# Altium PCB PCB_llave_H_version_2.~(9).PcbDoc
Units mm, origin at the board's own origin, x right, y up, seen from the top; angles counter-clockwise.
Board outline 98.1 x 71.5 mm, 2 copper layers (Top Layer, Bottom Layer); 62 components, 35 nets, 186 pads, 5 vias.
Unrouted connection lines stored in the file: 45.
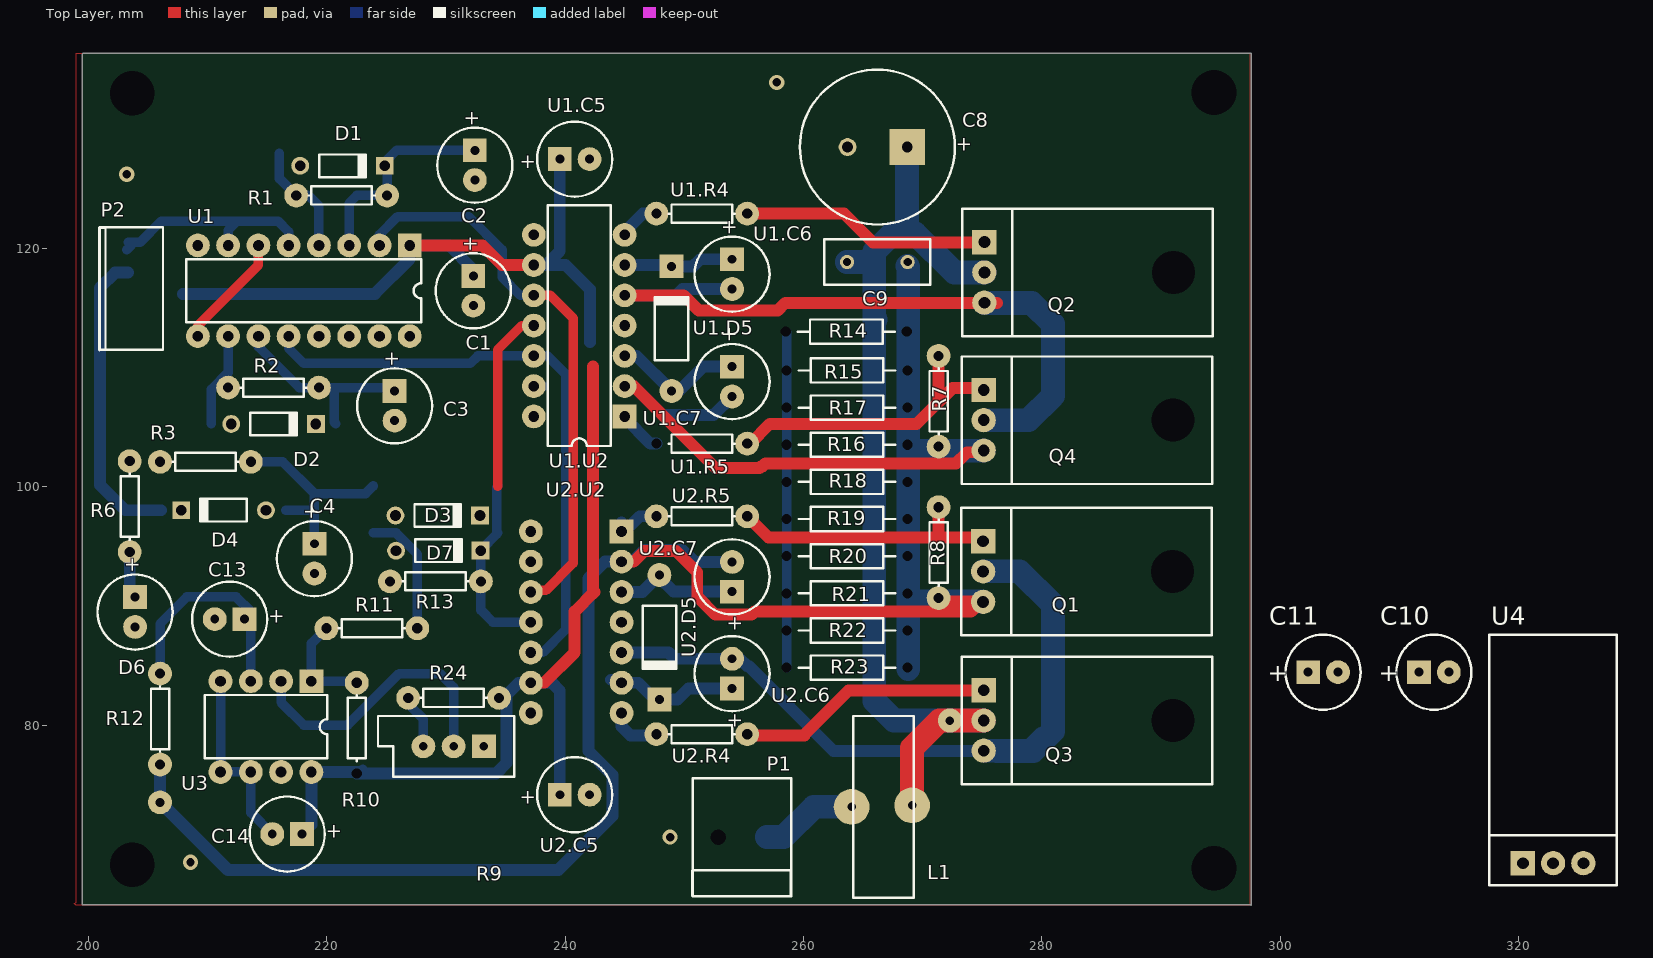
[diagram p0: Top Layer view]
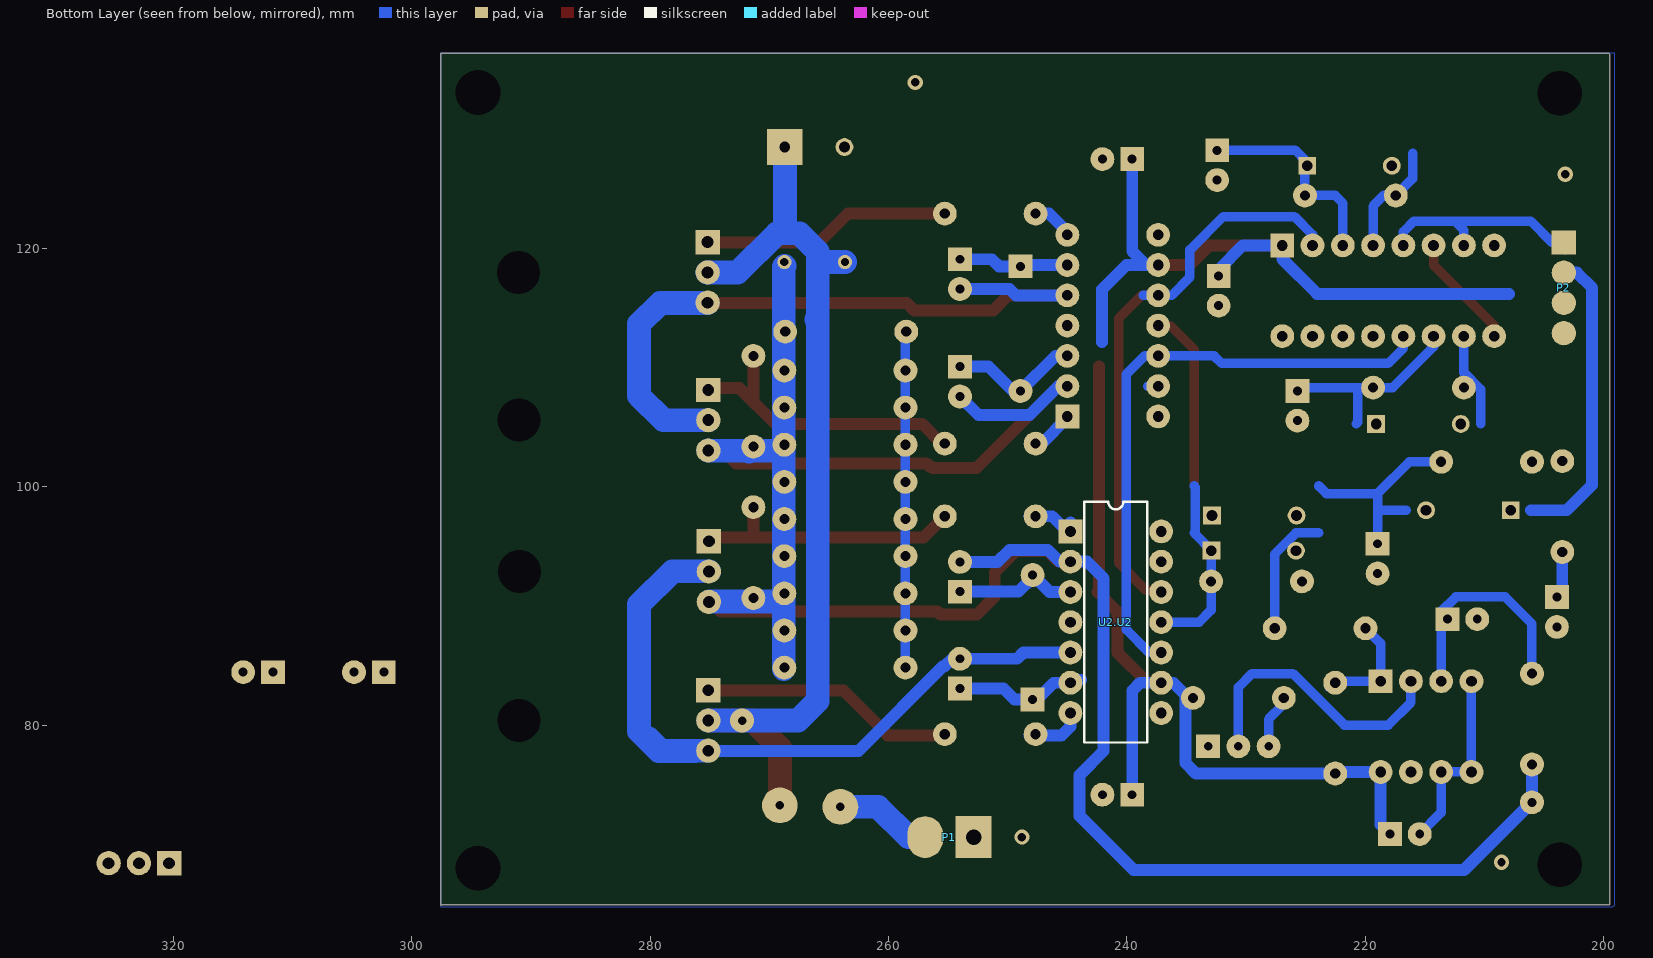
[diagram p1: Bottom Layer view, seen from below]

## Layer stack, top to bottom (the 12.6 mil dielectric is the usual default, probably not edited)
Top Layer: signal copper 0.0356
Dielectric: dielectric 0.32, FR-4, Dk 4.8
Bottom Layer: signal copper 0.0356

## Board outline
199.55,136.4 297.55,136.4 297.55,64.9 297.5,64.95 199.45,64.95 199.45,136.3

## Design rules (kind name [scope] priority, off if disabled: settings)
Clearance [All] p1: gap=0.4
ComponentClearance [All] p1: gap=0.254 collisioncheckmode=2 verticalgap=0.254
PlaneConnect [All] p1: planeconnectstyle=Direct reliefexpansion=0.508 reliefentries=4 reliefconductorwidth=0.254 reliefairgap=0.254
PolygonConnect [All] p1: connectstyle=Direct reliefconductorwidth=0.254 reliefentries=4 polygonreliefangle="90 Angle"
RoomDefinition U_regulador [InComponentClass('U_regulador')] p1: confinementstyle=ConfineIn formatcopy=TRUE lockcomponents=FALSE outline 298.649,66.3 328.499,66.3 328.499,90.4 298.649,90.4
RoomDefinition U2 [InComponentClass('U2')] p2: confinementstyle=ConfineIn formatcopy=TRUE lockcomponents=FALSE outline 276.86,69.723 229.616,69.723 229.616,109.474 276.86,109.474
RoomDefinition U1 [InComponentClass('U1')] p3: confinementstyle=ConfineIn formatcopy=TRUE lockcomponents=FALSE outline 271.272,133.604 230.759,133.604 230.759,101.981 271.272,101.981
RoomDefinition U_Puente_H [InComponentClass('U_Puente_H')] p4: confinementstyle=ConfineIn formatcopy=TRUE lockcomponents=FALSE outline 297.3,135.255 297.3,64.897 247.65,64.897 247.65,135.255
RoomDefinition U_INITShutdown [InComponentClass('U_INITShutdown')] p5: confinementstyle=ConfineIn formatcopy=TRUE lockcomponents=FALSE outline 199.45,106.045 199.45,90.297 236.347,90.297 236.347,106.045
RoomDefinition U_Shutdown [InComponentClass('U_Shutdown')] p6: confinementstyle=ConfineOut formatcopy=TRUE lockcomponents=FALSE outline 201.041,103.886 202.438,103.886 202.438,100.584 201.041,100.584
RoomDefinition Llave_H_esquema [InComponentClass('Llave_H_esquema')] p7: confinementstyle=ConfineIn formatcopy=TRUE lockcomponents=FALSE outline 199.4,64.897 297.55,64.897 297.55,136.398 199.4,136.398
RoomDefinition U_4049 [InComponentClass('U_4049')] p8: confinementstyle=ConfineIn formatcopy=TRUE lockcomponents=FALSE outline 206.375,101.473 240.411,101.473 240.411,131.953 206.375,131.953
RoutingVias [All] p1: holewidth=0.711 width=1.27 viastyle="Through Hole" minholewidth=0.711 minwidth=1.27 maxholewidth=0.711 maxwidth=1.27
SolderMaskExpansion [All] p1: expansion=0.102
TestPointUsage [All] p1: valid=0 allowmultiple=FALSE
Testpoint [All] p1: side=15 testpointundercomponent=TRUE minsize=1.016 maxsize=2.54 preferedsize=1.524 minholesize=0 maxholesize=1.016 preferedholesize=0.813 testpointgrid=0.025 style=1023 order=0-112345678
Width [All] p1: maxlimit=3 minlimit=0.8 preferedwidth=1
17 further rules are at their usual default settings.

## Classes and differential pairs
component class U_regulador: C10 C11 U4
component class U2: D5 U2.C5 U2.C6 U2.C7 U2.D5 U2.R4 U2.R5 U2.U2 U_2.D5 U_2_C5 U_2_C6 U_2_C7 U_2_R4 U_2_R5 U_2_U2
component class U1: U1.C5 U1.C6 U1.C7 U1.D5 U1.R4 U1.R5 U1.U2 U_1_C5 U_1_C6 U_1_C7 U_1_D5 U_1_R4 U_1_R5 U_1_U2
component class U_INITShutdown: C4 D3 D4 R3
channel class IR2110: U1 U2
component class U_Shutdown: C13 C14 D7 R9 R10 R11 R12 R13 R14 R15 R16 R17 R18 R19 R20 R21 R22 R23 R24 U3
component class U_Puente_H: C8 C9 L1 Q1 Q2 Q3 Q4 R7 R8
component class U_4049: C1 C2 C3 D1 D2 R1 R2 U1
component class Llave_H_esquema: D6 P1 P2 R6

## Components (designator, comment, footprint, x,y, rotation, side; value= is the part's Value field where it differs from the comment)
C1 "Cap Pol1 0.1u" CAPPR2.5-6.3X5 232.283,116.459 r270 top
C2 "Cap Pol1" CAPPR2.5-6.3X5 232.41,127 r270 top
C3 "Cap Pol1" CAPPR2.5-6.3X5 225.679,106.807 r270 top
C4 "Cap Pol1 4.7u" CAPPR2.5-6.3X5 218.948,93.98 r270 top
C8 "Cap Pol1" CAPPR5-13X16 266.192,128.524 r180 top
C9 "Cap" RAD-0.2 266.192,118.872 r180 top
C10 "Cap Pol1 0.1u" CAPPR2.5-6.3X5 312.899,84.45 r0 top
C11 "Cap Pol1 0.1u" CAPPR2.5-6.3X5 303.599,84.45 r0 top
C13 "Cap Pol1 4.7u" CAPPR2.5-6.3X5 211.836,88.9 r180 top
C14 "Cap Pol1 0.1u" CAPPR2.5-6.3X5 216.662,70.866 r180 top
D1 "Diode1" DO-35 221.3,126.95 r0 top
D2 "Diode1" DO-35 215.519,105.283 r0 top
D3 "Diode1" DO-35 229.3,97.6 r0 top
D4 "Diode1" DO-35 211.328,98.044 r180 top
D6 "LED0" CAPPR2.5-6.3X5 203.9,89.5 r270 top
D7 "Diode1" DO-35 229.35,94.65 r0 top
L1 "Inductor" bobina_Choque 264.16,75.692 r270 top
P1 "Header 2" pwheader1x2 255.016,70.612 r0 top
P2 "Header 4" HDR1X5 195.7,112.9 r270 top
Q1 "IRF3205" TO_220_H 284.9,82.05 r270 top
Q2 "IRF3205" TO_220_H 284.95,119.65 r270 top
Q3 "IRF3205" TO_220_H 284.85,94.55 r270 top
Q4 "IRF3205" TO_220_H 284.9,107.25 r270 top
R1 "18k" AXIAL-0.3#1 221.234,124.46 r180 top
R2 "18k" AXIAL-0.3#1 215.519,108.331 r0 top
R3 "4.7k" AXIAL-0.3#1 209.804,102.108 r180 top
R6 "1.2k" AXIAL-0.3#1 203.45,98.35 r90 top
R7 "6.8" AXIAL-0.3#1 271.33,107.188 r90 top
R8 "6.8" AXIAL-0.3#2 271.33,94.488 r90 top
R9 "RPot" VR5 230.632,78.232 r180 top
R10 "3.3k" AXIAL-0.3#3 222.504,79.756 r270 top
R11 "470" AXIAL-0.3#1 223.774,88.138 r0 top
R12 "6.8" AXIAL-0.3#1 205.994,80.518 r90 top locked
R13 "10k" AXIAL-0.3#1 229.108,92.075 r0 top
R14 "Res2" AXIAL-0.4#1 263.585,113.03 r0 top
R15 "Res2" AXIAL-0.4#1 263.652,109.774 r0 top
R16 "Res2" AXIAL-0.4#1 263.652,106.657 r0 top
R17 "Res2" AXIAL-0.4#1 263.652,103.539 r0 top
R18 "Res2" AXIAL-0.4#1 263.652,100.422 r0 top
R19 "Res2" AXIAL-0.4#1 263.652,97.305 r0 top
R20 "Res2" AXIAL-0.4#2 263.652,94.188 r0 top
R21 "Res2" AXIAL-0.4#2 263.652,91.07 r0 top
R22 "Res2" AXIAL-0.4#2 263.652,87.953 r0 top
R23 "Res2" AXIAL-0.4#2 263.652,84.836 r0 top
R24 "6.8" AXIAL-0.3#1 230.632,82.296 r0 top
U1 "MC54HC4049J" 620-09 218.059,116.459 r180 top
U1.C5 "Cap Pol1 4.7u" CAPPR2.5-6.3X5 240.792,127.508 r0 top (schematic designator C5)
U1.C6 "Cap Pol1" CAPPR2.5-6.3X5 254,117.856 r270 top (schematic designator C6)
U1.C7 "Cap Pol1" CAPPR2.5-6.3X5 254,108.839 r270 top (schematic designator C7)
U1.D5 "Diode" DO-204AL 248.92,113.284 r90 top (schematic designator D5)
U1.R4 "10" AXIAL-0.3#1 251.46,122.936 r0 top (schematic designator R4)
U1.R5 "10" AXIAL-0.3#4 251.46,103.632 r0 top (schematic designator R5)
U1.U2 "IR2110" PDIP14 241.173,113.538 r90 top (schematic designator U2)
U2.C5 "Cap Pol1 4.7u" CAPPR2.5-6.3X5 240.792,74.168 r0 top (schematic designator C5)
U2.C6 "Cap Pol1" CAPPR2.5-6.3X5 254,84.328 r90 top (schematic designator C6)
U2.C7 "Cap Pol1" CAPPR2.5-6.3X5 254,92.456 r90 top (schematic designator C7)
U2.D5 "Diode" DO-204AL 247.904,87.376 r270 top (schematic designator D5)
U2.R4 "10" AXIAL-0.3#1 251.46,79.248 r0 top (schematic designator R4)
U2.R5 "10" AXIAL-0.3#1 251.46,97.536 r0 top (schematic designator R5)
U2.U2 "IR2110" PDIP14 240.919,88.646 r270 bottom (schematic designator U2)
U3 "LM393N" 626-05 214.884,79.883 r180 top
U4 "µA7805CKC" To_220_H 321.249,78.2 r0 top

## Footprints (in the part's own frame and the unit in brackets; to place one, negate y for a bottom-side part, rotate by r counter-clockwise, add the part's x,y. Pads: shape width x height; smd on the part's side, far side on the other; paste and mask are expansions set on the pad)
620-09 [mm] "DIP; 16 Leads; Row Spacing 7.62 mm; Pitch 2.54 mm"
  rect 2x2 hole 0.9: 1(-8.89,-3.81)
  round 2 hole 0.9: 2(-6.35,-3.81) 3(-3.81,-3.81) 4(-1.27,-3.81) 5(1.27,-3.81) 6(3.81,-3.81) 7(6.35,-3.81) 8(8.89,-3.81) 9(8.89,3.81) 10(6.35,3.81) 11(3.81,3.81) 12(1.27,3.81) 13(-1.27,3.81) 14(-3.81,3.81) 15(-6.35,3.81) 16(-8.89,3.81)
  silkscreen extent -9.85,-2.65 9.85,2.65
626-05 [mm] "DIP; 8 Leads; Row Spacing 7.62 mm; Pitch 2.54 mm"
  rect 2x2 hole 0.9: 1(-3.81,-3.81)
  round 2 hole 0.9: 2(-1.27,-3.81) 3(1.27,-3.81) 4(3.81,-3.81) 5(3.81,3.81) 6(1.27,3.81) 7(-1.27,3.81) 8(-3.81,3.81)
  silkscreen extent -5.15,-2.65 5.15,2.65
AXIAL-0.3#1 [mm] "Resistor; 2 Leads"
  round 2 hole 0.85: 1(-3.81,0) 2(3.81,0)
  silkscreen extent -2.77,-0.76 2.77,0.76
AXIAL-0.3#2 [mm] "Resistor; 2 Leads"
  round 2 hole 0.85 paste+0 mask+0.102: 1(-3.81,0)
  round 2 hole 0.85: 2(3.81,0)
  silkscreen extent -2.77,-0.76 2.77,0.76
AXIAL-0.3#3 [mm] "Resistor; 2 Leads"
  round 2 hole 0.85: 1(-3.81,0)
  round 0 / inner round 0 / far side round 2 hole 0.85: 2(3.81,0)
  silkscreen extent -2.77,-0.76 2.77,0.76
AXIAL-0.3#4 [mm] "Resistor; 2 Leads"
  round 0 / inner round 0 / far side round 2 hole 0.85: 1(-3.81,0)
  round 2 hole 0.85: 2(3.81,0)
  silkscreen extent -2.77,-0.76 2.77,0.76
AXIAL-0.4#1 [mm] "Resistor; 2 Leads"
  round 0 / inner round 0 / far side round 2 hole 0.85: 1(-5.08,0) 2(5.08,0)
  silkscreen extent -4.06,-1.02 4.06,1.02
AXIAL-0.4#2 [mm] "Resistor; 2 Leads"
  round 0 / inner round 0 / far side round 2 hole 0.85: 1(-5.08,0)
  round 0 / inner round 0 / far side round 2 hole 0.85 unplated: 2(5.08,0)
  silkscreen extent -4.06,-1.02 4.06,1.02
bobina_Choque [mm]
  round 3 hole 0.7: 1(2.54,-0.127) 2(2.413,4.953)
  silkscreen extent -5.08,0 10.16,5.08
CAPPR2.5-6.3X5 [mm] "Capacitor, Electrolytic, Radial; Body 6.3 x 5 mm (Dia.xH typ); Pin Spacing 2.5 mm (typ)"
  rect 2x2 hole 0.75: 1(-1.25,0)
  round 2 hole 0.75: 2(1.25,0)
  silkscreen extent -3.15,-3.15 3.15,3.15
CAPPR5-13X16 [mm] "Capacitor, Electrolytic, Radial; Body 13 x 16 mm (Dia.xH typ); Pin Spacing 5 mm (typ)"
  rect 3x3 hole 0.9: 1(-2.5,0)
  round 1.5 hole 0.9: 2(2.5,0)
  silkscreen extent -6.5,-6.5 6.5,6.5
DO-35 [mm] "Diode, Axial; Body 3.8 x 1.9 mm (LxDia. max), Lead Dia. 0.53 mm (max)"
  round 1.5 hole 0.9: 1(-3.55,0)
  rect 1.5x1.5 hole 0.9: 2(3.55,0)
  silkscreen extent -1.95,-0.95 2.05,0.95
DO-204AL [mm] "Diode, Axial; Body 5.2 x 2.7 mm (LxDia. max), Lead Dia. 0.86 mm (max)"
  round 2 hole 0.75: 1(-5.23,0)
  rect 2x2 hole 0.75: 2(5.23,0)
  silkscreen extent -2.65,-1.41 2.75,1.4
HDR1X5 [mil]
  rect 80x80 smd far side: 1(-300,300)
  round 80 smd far side: 2(-200,300) 3(-100,300) 4(0,300)
  silkscreen extent -350,205 55,415
PDIP14 [mm] "DIP; 14 Leads; Row Spacing 7.62 mm; Pitch 2.54 mm"
  rect 2x2 hole 0.9: 1(-7.62,-3.81)
  round 2 hole 0.9: 2(-5.08,-3.81) 3(-2.54,-3.81) 4(0,-3.81) 5(2.54,-3.81) 6(5.08,-3.81) 7(7.62,-3.81) 8(7.62,3.81) 9(5.08,3.81) 10(2.54,3.81) 11(0,3.81) 12(-2.54,3.81) 13(-5.08,3.81) 14(-7.62,3.81)
  silkscreen extent -10.1,-2.65 10.1,2.65
pwheader1x2 [mm]
  round 0 / inner round 0 / far side rect 3x3.5 hole 1.3: 1(-2.159,0)
  oval 3x3.5 smd far side: 2(1.905,0)
  silkscreen extent -4.32,-4.95 3.94,4.95
RAD-0.2 [mm] "Jumper Wire; 2 Leads"
  round 1.2 hole 0.7: 1(-2.54,0) 2(2.54,0)
  silkscreen extent -4.44,-1.91 4.44,1.91
TO_220_H [mil] "to-220 horizontal"
  rect 80x80 hole 39.37: 1(-35,-385)
  round 80 hole 39.37: 2(65,-385) 3(165,-385)
  round 80 hole 141.73: 4(65,240)
  silkscreen extent -146,-458 276,370
To_220_H [mil] "to-220 horizontal"
  rect 80x80 hole 39.37: 1(-35,-385)
  round 80 hole 39.37: 2(65,-385) 3(165,-385)
  round 80 hole 141.73: 4(65,240)
  silkscreen extent -146,-458 276,370
VR5 [mm] "Potentiometer; 3 Leads"
  rect 2x2 hole 0.7: 1(-2.54,0)
  round 2 hole 0.7: 2(2.54,0) 3(0,0)
  silkscreen extent -5.08,-2.54 6.35,2.54

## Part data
C1 C4 C10 C11 C14 U1.C5 U2.C5: library part "Cap Pol1", "Polarized Capacitor (Radial)"
C2 C3 C8 U1.C6 U1.C7 U2.C6 U2.C7: "Polarized Capacitor (Radial)"
C9: "Capacitor"
C13: library part "Cap Pol1", "Polarized 16V"
D1 D2: library part Diode, "1N4148"
D3 D4 D7: library part Diode, "1n4148"
D6: "Typical INFRARED GaAs LED"
P1: "Header, 2-Pin"
P2: "Header, 4-Pin"
Q1 Q2 Q3 Q4: "HEXFET Power MOSFET"
R1 R2 R3 R6 R7 R8 R24 U1.R4 U1.R5 U2.R4 U2.R5: library part Res2, "Resistor"
R9: "Potenciomentro multivuelta"
R10 R11 R12 R13: library part Res2, "metal film 1/2 W"
R14 R15 R16 R17 R18 R19 R20 R21 R22 R23: "metal film 1W"
U1: "Hex Inverting Buffer/Logic-Level Down Converter"
U1.D5 U2.D5: "1N5819"
U1.U2 U2.U2: "High and Low Side Driver"
U3: "Dual Comparator"
U4: "Positive-Voltage Regulator"

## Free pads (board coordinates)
  round 1.524 hole 3.75: 0(203.65,68.3) 0(203.65,133.05) 0(294.45,68) 0(294.45,133.096)
  round 2 hole 0.762: 1(205.994,73.533)

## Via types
v1: diameter 1.27, hole 0.711, Top Layer to Bottom Layer, 4 vias
v2: diameter 2, hole 0.711, Top Layer to Bottom Layer, 1 vias

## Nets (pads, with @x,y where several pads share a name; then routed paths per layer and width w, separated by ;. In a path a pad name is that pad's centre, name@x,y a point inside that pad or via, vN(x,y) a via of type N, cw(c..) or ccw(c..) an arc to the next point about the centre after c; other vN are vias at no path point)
COMMON: C9.1 pad.1 Q3.3 Q4.3 R7.1 R8.1 R12.1 R14.2 R15.2 R16.2 R17.2 R18.2 R19.2 R20.2 R21.2 R22.2 R23.2 U1.C7.2 U1.U2.2 U2.C7.2 U2.U2.2 | length 208.1
  Top Layer w1: U2.U2.2 245.745,93.726 246.634,94.615 249.301,94.615 251.079,92.837 251.079,90.805 252.603,89.281 255.646,89.281 255.9,89.535 274.066,89.535 Q3.3@274.913,90.382 ; U1.U2.2 245.745,108.458 252.603,101.6 256.286,101.6 256.413,101.727 256.54,101.727 256.794,101.981 272.796,101.981 273.727,102.912 Q4.3@275.121,102.912 ; R8.1@271.78,90.382 Q3.3@275.071,90.382
  Bottom Layer w1: R12.1 205.994,73.556 211.7,67.85 239.427,67.85 243.967,72.39 243.967,75.819 241.935,77.851 241.935,92.329 243.332,93.726 245.633,93.726 246.629,94.722 249.829,94.722 250.845,93.706 U2.C7.2 ; U1.U2.2 245.745,108.458 248.158,106.045 252.456,106.045 U1.C7.2 ; R7.1@271.713,102.997 R7.1@271.798,102.912
  Bottom Layer w2: C9.1@268.732,118.526 268.792,118.465 R23.2@268.792,84.709 ; R21.2@268.792,90.382 Q3.3@275,90.382 ; R17.2@268.792,103.031 Q4.3 ; R7.1@271.713,102.965 R7.1@271.78,103.031
GND: C1.2 C2.2 C3.2 C4.2 C8.2 C10.2 C11.2 C13.2 C14.2 D6.2 P1.1 P2.3 pad.0 R9.1 R13.1 R14.1 R15.1 R16.1 R17.1 R18.1 R19.1 R20.1 R21.1 R22.1 R23.1 U1.8 U1.C5.2 U1.U2.13 U2.C5.2 U2.U2.13 U3.4 U3.5 U3.6 U4.2 | length 45.2
  Top Layer w0.8: U3.5 211.094,76.093 U3.5@211.074,76.113 ; U3.6@213.594,76.093 U3.6
  Bottom Layer w0.8: U3.5 U3.4 ; U3.5@211.094,76.093 U3.6@213.594,76.093 ; U3.6 213.614,72.664 C14.2 ; U1.U2.13 U1.U2.13@238.252,108.458 ; R23.1 R14.1@258.572,112.963
  other v1: 208.55,68.5 248.793,70.612 203.2,126.238 257.75,133.95
HO1: Q2.1 U1.R4.2 | length 20.9
  Top Layer w1: U1.R4.2 263.398,122.936 265.811,120.523 Q2.1@275.171,120.523
HO2: Q1.1 U2.R4.2 | length 20.9
  Top Layer w1: U2.R4.2@255.905,79.121 260.096,79.121 ; 259.969,79.121 263.779,82.931 Q1.1@275.121,82.931
IN_SD: D4.2 P2.2 | length 25.5
  Bottom Layer w1: P2.2 202.23,117.98 200.95,116.7 200.95,100.167 203.073,98.044 206.098,98.044
LO1: Q4.1 R7.2 U1.R5.2 | length 26
  Top Layer w1: U1.R5.2 255.524,103.632 257.175,105.283 269.494,105.283 272.511,108.3 274.813,108.3 Q4.1@275.121,107.992 ; 271.33,107.119 R7.2 ; R7.2@271.78,110.998 R7.2@271.78,111.252
LO2: Q3.1 R8.2 U2.R5.2 | length 23.2
  Top Layer w1: U2.R5.2@255.778,97.536 255.778,97.028 257.048,95.758 Q3.1@275,95.758 ; 271.3,95.758 271.33,95.788 R8.2 ; R8.2@271.526,98.679 R8.2@271.78,98.425
MOTOR+: Q2.3 Q4.2 U1.C6.2 U1.U2.5 | length 60.4
  Top Layer w1: U1.U2.5 249.936,116.078 251.206,114.808 257.836,114.808 258.471,115.443 276.225,115.443
  Bottom Layer w1: U1.U2.5 249.301,116.078 249.829,116.606 U1.C6.2
  Bottom Layer w2: Q4.2 278.873,105.599 280.924,107.65 280.924,113.665 279.146,115.443 Q2.3@275.171,115.443
MOTOR-: Q1.3 Q3.2 U2.C6.2 U2.U2.5 | length 62.3
  Bottom Layer w1: U2.U2.5 248.666,86.106 249.194,85.578 254.655,85.578 255.255,84.978 255.382,84.978 262.509,77.851 Q1.3@275.121,77.851
  Bottom Layer w2: Q3.2@275.071,92.922 278.13,92.922 280.924,90.128 280.924,79.502 279.273,77.851 276.225,77.851 ; Q1.3 279.109,77.859 280.15,78.9
NetC2_1: C2.1 D1.2 R1.1 U1.3 | length 18.1
  Bottom Layer w0.8: U1.3 221.869,123.825 222.504,124.46 R1.1@225.425,124.46 ; R1.1@225.05,124.46 225.05,127.45 225.85,128.25 C2.1
NetC3_1: C3.1 D2.2 R2.2 U1.11 | length 17
  Bottom Layer w0.8: U1.11 214.249,111.76 217.678,108.331 225.405,108.331 C3.1 ; 220.599,108.331 220.599,105.433 220.749,105.283
NetC4_1: C4.1 D3.1 D4.1 R3.1 | length 18.2
  Bottom Layer w0.8: R3.1 216.281,102.108 218.948,99.441 ; 216.558,98.044 218.948,98.044 ; C4.1 218.948,99.441 ; 223.878,100.076 223.243,99.441 218.948,99.441
NetC13_1: C13.1 R12.2 U3.3 | length 19.1
  Bottom Layer w0.8: R12.2 205.994,88.519 208.24,90.765 212.384,90.765 213.614,89.535 U3.3
NetD1_1: D1.1 R1.2 U1.4 | length 9.7
  Bottom Layer w0.8: 216.004,128.016 216.004,125.88 R1.2 218.44,124.46 219.329,123.571 U1.4
NetD2_1: D2.1 R2.1 U1.10 | length 8
  Bottom Layer w0.8: 210.289,105.283 210.289,108.181 211.709,109.601 U1.10
NetD6_1: D6.1 R6.1 | length 4
  Bottom Layer w1: R6.1 203.45,91.2 D6.1
NetD7_1: D7.1 R11.2 | length 10.7
  Bottom Layer w0.8: 223.878,96.139 225.806,96.139 227.584,94.361 R11.2
NetR9_2: R9.2 R24.1 | length 4.8
  Bottom Layer w0.8: R24.1@226.949,82.55 226.949,81.661 228.092,80.518 R9.2
NetR9_3: R9.3 U3.2 | length 24.3
  Bottom Layer w0.8: U3.2 216.154,81.915 218.059,80.01 221.742,80.01 226.06,84.328 229.489,84.328 230.632,83.185 R9.3
NetR10_1: R10.1 R11.1 U3.1 | length 9.5
  Bottom Layer w0.8: R11.1 218.694,86.868 U3.1 222.504,83.693 R10.1@223.012,83.185
NetU1.C6_1: U1.C6.1 U1.D5.2 U1.U2.6 | length 9.8
  Bottom Layer w1: U1.U2.6 248.308,118.618 248.412,118.514 250.721,118.514 251.313,119.106 U1.C6.1 ; U1.D5.2@248.943,118.872 U1.D5.2@249.301,118.514
NetU1.R4_1: U1.R4.1 U1.U2.7 | length 3.8
  Bottom Layer w1: U1.U2.7 244.983,121.412 246.507,122.936 U1.R4.1@247.904,122.936
NetU1.R5_1: U1.R5.1 U1.U2.1 | length 3.7
  Bottom Layer w1: U1.U2.1 244.983,105.791 247.142,103.632 U1.R5.1
NetU1_6: U1.6 U1.9 | length 9.9
  Top Layer w0.8: U1.9 209.169,113.538 214.249,118.618 U1.6
  Bottom Layer w0.8: U1.9 U1.9@209.169,112.776
NetU2.C6_1: U2.C6.1 U2.D5.2 U2.U2.6 | length 10.8
  Bottom Layer w1: U2.U2.6@243.84,83.82 U2.U2.6@244.602,83.82 ; U2.U2.6 246.126,83.566 U2.D5.2@247.673,82.019 ; U2.D5.2 249.405,82.146 250.337,83.078 U2.C6.1
NetU2.R4_1: U2.R4.1 U2.U2.7 | length 4.9
  Bottom Layer w1: U2.U2.7 244.729,79.883 245.491,79.121 U2.R4.1@248.158,79.121
NetU2.R5_1: U2.R5.1 U2.U2.1 | length 4.7
  Bottom Layer w1: U2.U2.1@244.729,97.028 U2.U2.1 244.983,96.266 246.253,97.536 U2.R5.1@248.158,97.536
PWM: P2.1 U1.5 U1.7 | length 18.6
  Bottom Layer w0.8: P2.1@203.2,119.888 P2.1@203.576,120.264 ; P2.1 204.319,120.52 206.1,122.301 215.9,122.301 216.789,121.412 U1.5 ; U1.7 211.709,121.539 212.471,122.301
SD: D3.2 D7.2 R13.2 U1.U2.11 U2.U2.11 | length 31.1
  Top Layer w0.8: 234.338,100.076 234.338,111.529 236.347,113.538 U1.U2.11
  Bottom Layer w0.8: 234.241,96.042 234.241,99.979 234.338,100.076 ; 234.338,96.139 232.918,94.719 232.918,89.662 233.934,88.646 U2.U2.11
U1.HIN: U1.2 U1.U2.10 U2.U2.12 | length 48.9
  Top Layer w0.8: U2.U2.12@237.236,91.313 238.379,91.313 240.665,93.599 240.665,114.173 238.76,116.078 U1.U2.10
  Bottom Layer w0.8: U1.2 224.409,121.158 225.933,122.682 231.902,122.682 234.696,119.888 234.696,117.602 236.22,116.078 238.633,116.078
U1.LIN: U1.12 U1.U2.12 U2.U2.10 | length 50.9
  Bottom Layer w0.8: U1.12 216.789,111.633 218.059,110.363 232.029,110.363 232.664,110.998 238.506,110.998 240.03,109.474 240.03,88.011 238.125,86.106 U2.U2.10
VCC: C10.1 P2.4 R6.2 U1.C7.1 U1.D5.1 U1.U2.3 U2.C7.1 U2.D5.1 U2.U2.3 U4.1 | length 21.6
  Bottom Layer w1: U2.U2.3 246.484,91.186 U2.D5.1 247.904,92.396 249.094,91.206 U2.C7.1 ; U1.U2.3 245.976,110.998 U1.D5.1 249.554,108.054 251.589,110.089 U1.C7.1
VCC_MOTOR: L1.1 P1.2 | length 8.2
  Bottom Layer w2: P1.2 258.318,70.612 260.858,73.152 L1.1
VCC_MOTOR_FILTRADO: C8.1 C9.2 L1.2 Q1.2 Q2.2 | length 80.1
  Top Layer w2: L1.2 269.113,78.105 271.399,80.391 Q1.2@275.121,80.391
  Bottom Layer w2: C9.2 265.811,118.872 265.938,118.745 ; 265.938,113.919 266.065,114.046 ; 268.692,121.579 C8.1 ; Q1.2@275.121,80.391 267.589,80.391 265.938,82.042 265.938,119.761 267.462,121.285 269.367,121.285 272.669,117.983 Q2.2@275.171,117.983
  other v2: 272.288,80.391
VDD: C1.1 C11.1 C14.1 R3.2 R10.2 R24.2 U1.1 U1.C5.1 U1.U2.9 U2.C5.1 U2.U2.9 U3.8 U4.3 | length 131.6
  Top Layer w0.8: C14.1 C14.1@217.912,71.481 ; U3.8@218.567,76.327 218.694,76.2 U3.8
  Top Layer w1: U1.1 233.045,120.269 234.696,118.618 U1.U2.9 ; U2.U2.9 238.252,83.566 240.792,86.106 240.792,89.535 242.443,91.186 ; 242.316,91.059 242.316,110.109
  Bottom Layer w0.8: R10.2@222.994,76.309 R10.2@223.012,76.292 ; C1.1 C1.1@232.283,118.11
  Bottom Layer w1: 207.9,116.205 224.028,116.205 226.949,119.126 U1.1 230.251,120.269 232.283,118.237 C1.1 ; C14.1 218.694,71.648 U3.8 R10.2@222.758,76.073 ; R10.2 234.188,75.946 235.077,76.835 235.077,82.55 236.093,83.566 238.887,83.566 239.542,82.911 U2.C5.1 ; U1.U2.9 240.03,118.618 242.062,116.586 242.062,112.141 ; 238.379,118.618 239.542,119.781 U1.C5.1
pads on no net: Q1.4 Q2.4 Q3.4 Q4.4 U1.13 U1.14 U1.15 U1.16 U1.U2.4 U1.U2.8 U1.U2.14 U2.U2.4 U2.U2.8 U2.U2.14 U3.7 U4.4

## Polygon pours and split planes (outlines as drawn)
GND on Bottom Layer "Bottom Layer-GND" (solid, remove dead copper, shelved, pour order 1001): 199.05,136.398 297.55,136.398 297.55,64.77 199.195,64.77 199.05,64.897
GND on Top Layer "Top Layer-GND" (solid, remove dead copper, shelved, pour order 1000): 198.946,136.398 297.45,136.398 297.45,64.897 198.946,64.897 198.8,65.024 198.946,65.151

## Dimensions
258.064,52.578 to 207.391,218.567 on Top Layer
191.008,215.519 to 316.992,211.201 on Top Layer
